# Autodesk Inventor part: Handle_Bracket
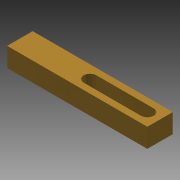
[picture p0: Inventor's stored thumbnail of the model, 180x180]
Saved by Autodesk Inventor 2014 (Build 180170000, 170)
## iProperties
Created: 2014-03
Part Number: Handle_Bracket
Material: Brass, Soft Yellow
Document SubType Name: Modeling
Designer: Beast
Density: 8.47 g/cm^3
Appearance: Brass - Satin
Author: Beast
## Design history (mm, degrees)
sketch "Sketch1"
  geometry: L1 (0, 0)-(69.85, 0); L2 (69.85, 0)-(69.85, 12.7); L3 (69.85, 12.7)-(0, 12.7); L4 (0, 12.7)-(0, 0)
  constraints: 8 end point, 2 parallel, 1 horizontal, 1 perpendicular
  dimensions: "d0" = 69.85 distance of L3.end L2.end; "d1" = 12.7 distance of L2.end L1.end
extrude "Extrusion1" new body sketch "Sketch1" distance "d2" = 9.525; taper "d3" = 0 deg
sketch "Sketch3"
  geometry: L1 (0, 0)-(-69.85, 0) reference; L2 (0, -12.7)-(0, 0) reference; L3 (-34.925, -6.35)-(-6.35, -6.35); L4 (-34.925, -9.525)-(-6.35, -9.525); L5 (-6.35, -3.175)-(-34.925, -3.175); A1 r 3.175 centre (-34.925, -6.35) between (-34.925, -3.175) and (-34.925, -9.525); A2 r 3.175 centre (-6.35, -6.35) between (-6.35, -9.525) and (-6.35, -3.175); 1 further point
  constraints: 8 end point, 4 point on circle, 4 tangent, 2 centre point, 2 parallel, 1 midpoint
  dimensions: "d8" = 28.575 distance of L3.end L3.start; "d9" = 6.35 distance from line of L2 L3.end; "d10" = 6.35 diameter of A2
extrude "Extrusion2" cut sketch "Sketch3" distance "d11" = 6.35; taper "d12" = 0 deg
body "Solid1"
